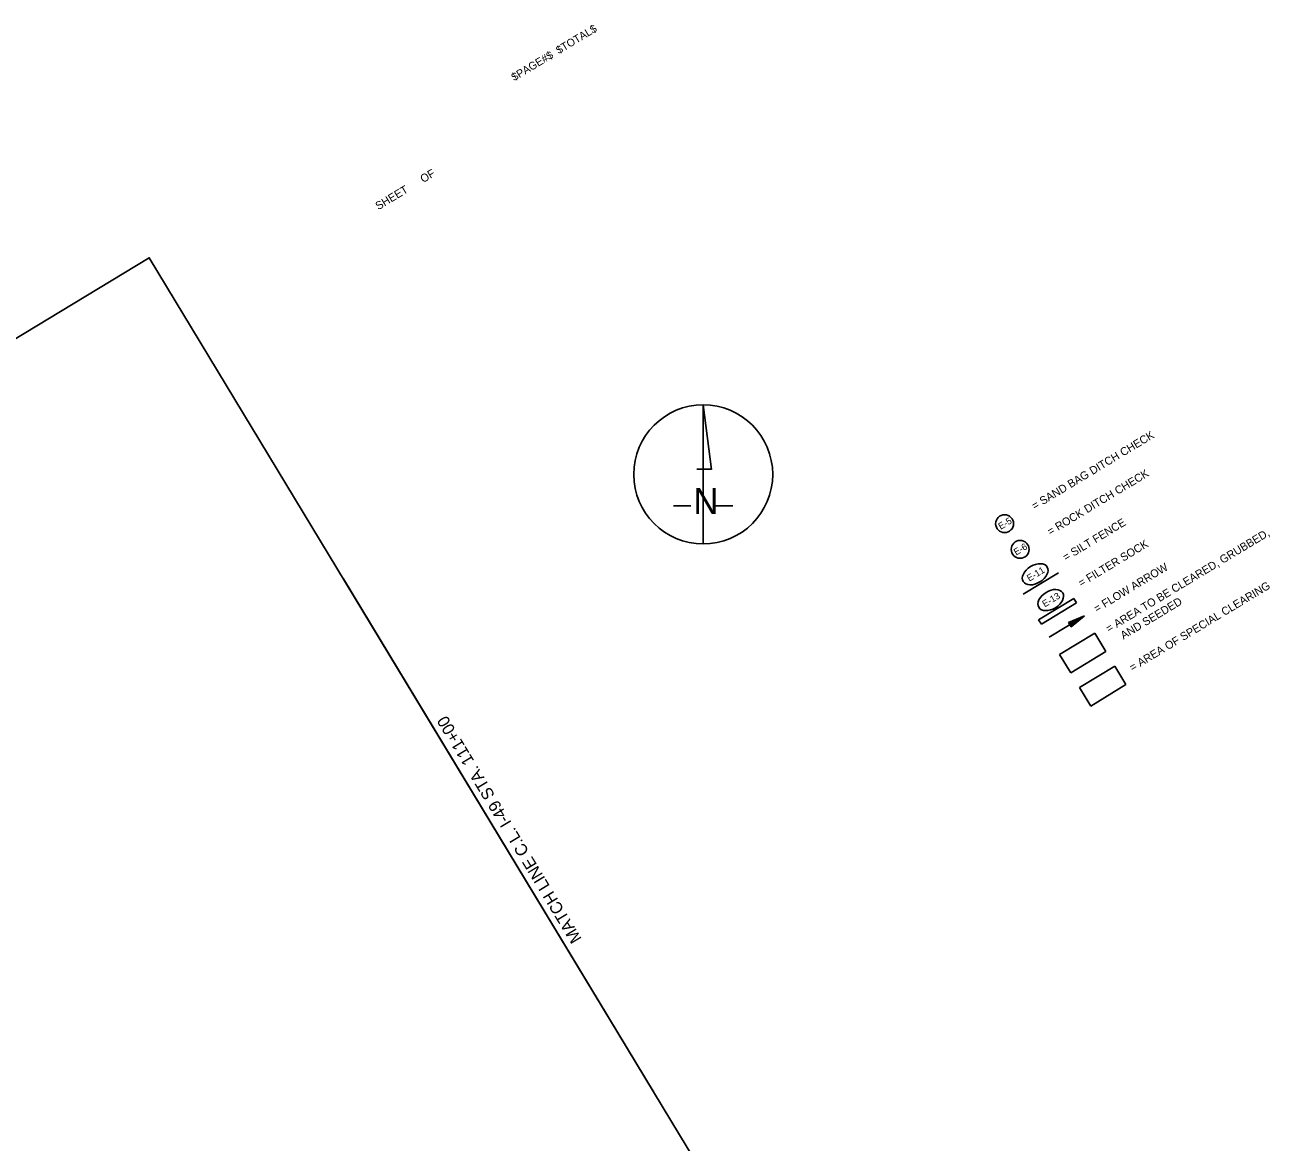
# Model space of a CAD drawing. Extents: x 627457 to 631191, y 366597 to 369946.
# Drawn here: x 629324 to 631191, y 368272 to 369946 of the extents above; entities that cross this region are included whole.
import ezdxf

# ---------------------------------------------------------------- set-up
doc = ezdxf.new("R2010")
doc.units = 0
for name, color, linetype in [('Copy of R_Dimension', 7, 'Continuous'), ('R_Draft', 7, 'Continuous'), ('R_Erosion_E6', 7, 'Continuous'), ('R_Horz Alg Side', 7, 'Continuous'), ('S_DITCHLINE', 7, 'Continuous'), ('S_ELECTRIC_UTILITIES', 7, 'Continuous')]:
    doc.layers.add(name, color=color, linetype=linetype)

# ---------------------------------------------------------------- blocks, each defined once
blk = doc.blocks.new('SHT-INFO-CELL_2 TITLE LINES')
at = {"layer": 'Copy of R_Dimension'}
for s, p in [('SHEET', (14.4405, 10.0545)), ('OF', (14.8333, 10.0545))]:
    blk.add_text(s, height=0.06, dxfattribs=at).set_placement(p)

msp = doc.modelspace()

# ---------------------------------------------------------------- linework, layer by layer
at = {"layer": 'Copy of R_Dimension'}
msp.add_line((630340.7, 369376.8), (630340.7, 369168.5), dxfattribs=at)
msp.add_lwpolyline([(630573.5, 367839.2), (629510.2, 369597.3), (629510.2, 369597.3), (627456.6, 368355.4), (628519.8, 366597.3)], close=True, dxfattribs=at)
msp.add_circle((630340.7, 369272.7), 104.2, dxfattribs=at)
at = {"layer": 'R_Draft'}
msp.add_line((630267.1, 368345.8), (629801.4, 369115.9), dxfattribs=at)
at = {"layer": 'R_Erosion_E6'}
for p, q in [((630340.7, 369376.8), (630352.9, 369279.9)), ((630340.7, 369241.2), (630340.7, 369376.8)), ((630331.3, 369280.6), (630352.9, 369280.6)), ((630296.1, 369225.3), (630321.9, 369225.3)), ((630357.8, 369225.3), (630385.3, 369225.3)), ((630340.7, 369168.5), (630340.7, 369208.4))]:
    msp.add_line(p, q, dxfattribs=at)
at = {"layer": 'R_Horz Alg Side'}
for p, q in [((630896.5, 369086.8), (630843.6, 369054.8)), ((630896.5, 369086.8), (630899.5, 369081.7)), ((630900.5, 369080), (630896.5, 369086.8)), ((630900.5, 369080), (630847.7, 369048)), ((630847.7, 369048), (630900.5, 369080)), ((630847.7, 369048), (630843.6, 369054.8)), ((630843.6, 369054.8), (630847.7, 369048)), ((630912.2, 369060.8), (630859.3, 369028.8)), ((630888.4, 369050.9), (630912.2, 369060.8)), ((630888.4, 369050.9), (630892.3, 369044.3)), ((630888.7, 369050.3), (630908.5, 369058.6)), ((630889, 369049.8), (630904.8, 369056.3)), ((630889.4, 369049.2), (630901.1, 369054.1)), ((630889.7, 369048.7), (630897.4, 369051.9)), ((630890, 369048.1), (630893.8, 369049.7)), ((630890.6, 369047.1), (630893.8, 369049.7)), ((630891, 369046.5), (630897.4, 369051.9)), ((630891.3, 369046), (630901.1, 369054.1)), ((630891.7, 369045.4), (630904.8, 369056.3)), ((630892, 369044.9), (630908.5, 369058.6)), ((630892.3, 369044.3), (630912.2, 369060.8)), ((630875, 369002.8), (630927.9, 369034.8)), ((630927.9, 369034.8), (630875, 369002.8)), ((630927.9, 369034.8), (630944.6, 369007.2)), ((630944.6, 369007.2), (630927.9, 369034.8)), ((630891.7, 368975.2), (630875, 369002.8)), ((630875, 369002.8), (630891.7, 368975.2)), ((630944.6, 369007.2), (630891.7, 368975.2)), ((630891.7, 368975.2), (630944.6, 369007.2)), ((630905, 368953.2), (630957.9, 368985.1)), ((630957.9, 368985.1), (630974.6, 368957.5)), ((630921.8, 368925.5), (630905, 368953.2)), ((630974.6, 368957.5), (630921.8, 368925.5))]:
    msp.add_line(p, q, dxfattribs=at)
msp.add_lwpolyline([(630843.6, 369054.8), (630896.5, 369086.8)], dxfattribs=at)
for centre in [(630792.6, 369198.8), (630815.9, 369160.3)]:
    msp.add_circle(centre, 13.4, dxfattribs=at)
for centre in [(630838.5, 369122.9), (630861.8, 369084.3)]:
    msp.add_ellipse(centre, major_axis=(18, 10.9), ratio=0.638788, dxfattribs=at)
at = {"layer": 'S_DITCHLINE'}
msp.add_lwpolyline([(630820.3, 369093.3), (630873.2, 369125.3)], dxfattribs=at)
at = {"layer": 'S_ELECTRIC_UTILITIES'}
for p, q in [((630957.9, 368985.1), (630905, 368953.2)), ((630974.6, 368957.5), (630957.9, 368985.1)), ((630905, 368953.2), (630921.8, 368925.5)), ((630921.8, 368925.5), (630974.6, 368957.5))]:
    msp.add_line(p, q, dxfattribs=at)

# ---------------------------------------------------------------- block references
at = {"layer": 'Copy of R_Dimension'}
for xscale, yscale, rotation in [(200.00000000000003, 199.99999999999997, 31.163843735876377), (199.99999999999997, 199.99999999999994, 31.163843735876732)]:
    msp.add_blockref('SHT-INFO-CELL_2 TITLE LINES', (628423, 366453.3), dxfattribs=dict(at, xscale=xscale, yscale=yscale, rotation=rotation))

# ---------------------------------------------------------------- texts
at = {"layer": 'R_Draft'}
for s, p in [('$TOTAL$', (630124.4, 369902.4)), ('$PAGE#$', (630057.5, 369861.9))]:
    msp.add_text(s, height=11.72, rotation=31.1638, dxfattribs=at).set_placement(p)
at = {"layer": 'R_Erosion_E6'}
msp.add_text('N', height=38.8, rotation=360, dxfattribs=at).set_placement((630326, 369213.3))
at = {"layer": 'R_Horz Alg Side'}
for s, p in [('E-5', (630786.8, 369189.5)), ('E-6', (630810, 369150.9)), ('E-11', (630829.7, 369111.8)), ('E-13', (630852.8, 369073.2))]:
    msp.add_text(s, height=10, rotation=31.1638, dxfattribs=at).set_placement(p)
at = {"layer": 'S_DITCHLINE'}
msp.add_text('MATCH LINE C.L. I-49 STA. 111+00', height=18, rotation=121.1638, dxfattribs=at).set_placement((630159.1, 368576.6))
at = {"layer": 'S_ELECTRIC_UTILITIES'}
for s, p in [('= SAND BAG DITCH CHECK', (630837.8, 369219.2)), ('= ROCK DITCH CHECK', (630861.1, 369180.7)), ('= SILT FENCE', (630884.4, 369142.2)), ('= AREA TO BE CLEARED, GRUBBED,', (630949, 369035.2)), ('= FILTER SOCK', (630907.6, 369103.6)), ('= FLOW ARROW', (630930.9, 369065.1)), ('= AREA OF SPECIAL CLEARING', (630984.3, 368976.9)), ('   AND SEEDED', (630959.4, 369018.1))]:
    msp.add_text(s, height=12, rotation=31.1638, dxfattribs=at).set_placement(p)

doc.saveas('drawing.dxf')
